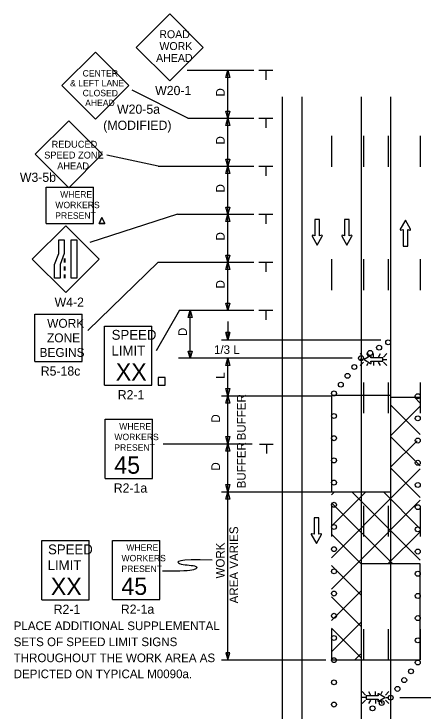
# Model space of a CAD drawing. Extents: x 16729 to 18475, y 5706 to 6927.
# Drawn here: x 16730 to 17062, y 6361 to 6927 of the extents above; entities that cross this region are included whole.
import ezdxf

# ---------------------------------------------------------------- set-up
doc = ezdxf.new("R2010")
doc.units = 0
for name, color, linetype in [('ALI_LEGAL_EX', 7, 'Continuous'), ('MT_SCRATCH_LEVEL_A', 7, 'Continuous'), ('MT_SCRATCH_LEVEL_E', 7, 'Continuous'), ('PAVT_EDGE_EX', 7, 'Continuous'), ('TRAFFIC_SIGNS_PR', 7, 'Continuous'), ('TYPICAL_TEXT_DIMEN_PR', 7, 'Continuous')]:
    doc.layers.add(name, color=color, linetype=linetype)

msp = doc.modelspace()

# ---------------------------------------------------------------- linework, layer by layer
at = {"layer": 'ALI_LEGAL_EX'}
for points in [[(16987.43, 6827.88), (16987.43, 6802.88)], [(17013.43, 6827.88), (17013.43, 6802.88)], [(17033.43, 6827.88), (17033.43, 6802.88)], [(17059.43, 6827.88), (17059.43, 6802.88)], [(16987.43, 6727.88), (16987.43, 6702.88)], [(17013.43, 6727.88), (17013.43, 6702.88)], [(17033.43, 6727.88), (17033.43, 6702.88)], [(17059.43, 6727.88), (17059.43, 6702.88)], [(17013.43, 6627.88), (17013.43, 6602.88)], [(17033.43, 6627.88), (17033.43, 6602.88)], [(17059.43, 6627.88), (17059.43, 6602.88)], [(16987.43, 6527.88), (16987.43, 6502.88)], [(17013.43, 6527.88), (17013.43, 6502.88)], [(17033.43, 6527.88), (17033.43, 6502.88)], [(17059.43, 6527.88), (17059.43, 6502.88)], [(16987.43, 6427.88), (16987.43, 6402.88)], [(17013.43, 6427.88), (17013.43, 6402.88)], [(17033.43, 6427.88), (17033.43, 6402.88)], [(17059.43, 6427.88), (17059.43, 6402.88)]]:
    msp.add_lwpolyline(points, dxfattribs=at)
at = {"layer": 'MT_SCRATCH_LEVEL_A'}
for p, q in [((17035.43, 6615.84), (17059.43, 6615.84)), ((17059.43, 6611.08), (17054.68, 6615.84)), ((17059.43, 6585.62), (17035.52, 6609.54)), ((17035.52, 6584.79), (17059.43, 6608.71)), ((17059.43, 6560.17), (17035.43, 6584.17)), ((17035.62, 6559.44), (17056.86, 6580.68)), ((17059.43, 6534.71), (17035.43, 6558.71)), ((17035.43, 6533.8), (17059.43, 6557.8)), ((16987.43, 6485.8), (17040.82, 6539.18)), ((16987.43, 6511.25), (17015.36, 6539.18)), ((16987.43, 6536.71), (16989.91, 6539.18)), ((17059.43, 6483.8), (17004.05, 6539.18)), ((17059.43, 6509.26), (17029.51, 6539.18)), ((17037.11, 6480.67), (16987.43, 6530.34)), ((17011.43, 6484.34), (17059.43, 6532.34)), ((17011.43, 6480.89), (16987.43, 6504.89)), ((17033.22, 6480.67), (17059.43, 6506.88)), ((16987.43, 6460.34), (17011.43, 6484.34)), ((17011.43, 6455.43), (16987.43, 6479.43)), ((16987.43, 6434.88), (17011.43, 6458.88)), ((17011.43, 6429.98), (16987.43, 6453.98)), ((16987.43, 6409.43), (17011.43, 6433.43)), ((17011.43, 6404.52), (16987.43, 6428.52)), ((17006.29, 6402.82), (17010.91, 6407.45)), ((16987.43, 6402.82), (17011.43, 6402.82))]:
    msp.add_line(p, q, dxfattribs=at)
at = {"layer": 'MT_SCRATCH_LEVEL_E'}
for p, q in [((16977.76, 6760.18), (16974.02, 6760.18)), ((16974.02, 6760.18), (16974.02, 6746.93)), ((16977.76, 6760.18), (16974.02, 6760.18)), ((16974.02, 6760.18), (16974.02, 6746.93)), ((16977.76, 6746.93), (16977.76, 6760.18)), ((16977.76, 6746.93), (16977.76, 6760.18)), ((17001.83, 6760.18), (16998.09, 6760.18)), ((16998.09, 6760.18), (16998.09, 6746.93)), ((17001.83, 6760.18), (16998.09, 6760.18)), ((16998.09, 6760.18), (16998.09, 6746.93)), ((17001.83, 6746.93), (17001.83, 6760.18)), ((17001.83, 6746.93), (17001.83, 6760.18)), ((17047.37, 6759.44), (17043.26, 6752.2)), ((17047.37, 6759.44), (17043.26, 6752.2)), ((17051.52, 6752.2), (17047.37, 6759.44)), ((17051.52, 6752.2), (17047.37, 6759.44)), ((17043.74, 6751.51), (17045.52, 6751.83)), ((17043.74, 6751.51), (17045.52, 6751.83)), ((17045.52, 6751.83), (17045.52, 6738.57)), ((17045.52, 6751.83), (17045.52, 6738.57)), ((17049.26, 6738.57), (17049.26, 6751.83)), ((17049.26, 6751.83), (17051.04, 6751.51)), ((17049.26, 6738.57), (17049.26, 6751.83)), ((17049.26, 6751.83), (17051.04, 6751.51)), ((16971.76, 6746.56), (16975.91, 6739.32)), ((16971.76, 6746.56), (16975.91, 6739.32)), ((16974.02, 6746.93), (16972.24, 6747.24)), ((16974.02, 6746.93), (16972.24, 6747.24)), ((16975.91, 6739.32), (16980.02, 6746.56)), ((16975.91, 6739.32), (16980.02, 6746.56)), ((16979.53, 6747.24), (16977.76, 6746.93)), ((16979.53, 6747.24), (16977.76, 6746.93)), ((16995.83, 6746.56), (16999.98, 6739.32)), ((16995.83, 6746.56), (16999.98, 6739.32)), ((16998.09, 6746.93), (16996.31, 6747.24)), ((16998.09, 6746.93), (16996.31, 6747.24)), ((16999.98, 6739.32), (17004.09, 6746.56)), ((16999.98, 6739.32), (17004.09, 6746.56)), ((17003.61, 6747.24), (17001.83, 6746.93)), ((17003.61, 6747.24), (17001.83, 6746.93)), ((17045.52, 6738.57), (17049.26, 6738.57)), ((17045.52, 6738.57), (17049.26, 6738.57)), ((16977.1, 6518.09), (16973.36, 6518.09)), ((16973.36, 6518.09), (16973.36, 6504.83)), ((16977.1, 6518.09), (16973.36, 6518.09)), ((16973.36, 6518.09), (16973.36, 6504.83)), ((16977.1, 6504.83), (16977.1, 6518.09)), ((16977.1, 6504.83), (16977.1, 6518.09)), ((16971.1, 6504.46), (16975.25, 6497.22)), ((16971.1, 6504.46), (16975.25, 6497.22)), ((16973.36, 6504.83), (16971.58, 6505.15)), ((16973.36, 6504.83), (16971.58, 6505.15)), ((16975.25, 6497.22), (16979.36, 6504.46)), ((16975.25, 6497.22), (16979.36, 6504.46)), ((16978.88, 6505.15), (16977.1, 6504.83)), ((16978.88, 6505.15), (16977.1, 6504.83))]:
    msp.add_line(p, q, dxfattribs=at)
for centre, start, end in [((17043.67, 6751.97), 150.4248, 279.9638), ((17043.67, 6751.97), 150.4248, 279.9638), ((17051.11, 6751.97), 260.0362, 29.7731), ((17051.11, 6751.97), 260.0362, 29.7731), ((16972.17, 6746.78), 80.0362, 209.7731), ((16972.17, 6746.78), 80.0362, 209.7731), ((16979.61, 6746.78), 330.4248, 99.9638), ((16979.61, 6746.78), 330.4248, 99.9638), ((16996.24, 6746.78), 80.0362, 209.7731), ((16996.24, 6746.78), 80.0362, 209.7731), ((17003.68, 6746.78), 330.4248, 99.9638), ((17003.68, 6746.78), 330.4248, 99.9638), ((16971.51, 6504.69), 80.0362, 209.7731), ((16971.51, 6504.69), 80.0362, 209.7731), ((16978.96, 6504.69), 330.4248, 99.9638), ((16978.96, 6504.69), 330.4248, 99.9638)]:
    msp.add_arc(centre, 0.463, start, end, dxfattribs=at)
at = {"layer": 'PAVT_EDGE_EX'}
for p, q in [((16947.43, 6859.63), (16947.43, 6100.51)), ((16963.43, 6859.63), (16963.43, 6100.51)), ((17011.43, 6859.63), (17011.43, 6100.51)), ((17035.43, 6859.63), (17035.43, 6100.51))]:
    msp.add_line(p, q, dxfattribs=at)
for points in [[(17035.52, 6617.36), (16987.43, 6617.36), (16987.43, 6539.18), (17035.52, 6539.18)], [(17059.43, 6480.67), (17011.43, 6480.67), (17011.43, 6402.82), (17059.43, 6402.82)]]:
    msp.add_lwpolyline(points, close=True, dxfattribs=at)
at = {"layer": 'TRAFFIC_SIGNS_PR'}
for p, q in [((16856.39, 6926.78), (16829.2, 6899.59)), ((16883.58, 6899.59), (16856.39, 6926.78)), ((16829.2, 6899.59), (16856.39, 6872.4)), ((16856.39, 6872.4), (16883.58, 6899.59)), ((16796.14, 6895.81), (16768.95, 6868.62)), ((16823.32, 6868.62), (16796.14, 6895.81)), ((16768.95, 6868.62), (16796.14, 6841.44)), ((16796.14, 6841.44), (16823.32, 6868.62)), ((16774.54, 6840.16), (16747.38, 6813.01)), ((16801.69, 6813.01), (16774.54, 6840.16)), ((16747.38, 6813.01), (16774.54, 6785.86)), ((16774.54, 6785.86), (16801.69, 6813.01)), ((16756.27, 6786.17), (16794.67, 6786.17)), ((16756.27, 6756.85), (16756.27, 6786.17)), ((16794.67, 6756.85), (16794.67, 6786.17)), ((16756.27, 6756.85), (16794.67, 6756.85)), ((16772.09, 6755.03), (16744.94, 6727.88)), ((16799.24, 6727.88), (16772.09, 6755.03)), ((16770.84, 6728.37), (16770.84, 6725.17)), ((16771.24, 6728.37), (16771.24, 6725.17)), ((16744.94, 6727.88), (16772.09, 6700.73)), ((16772.09, 6700.73), (16799.24, 6727.88)), ((16770.84, 6721.97), (16770.84, 6718.77)), ((16771.24, 6721.97), (16771.24, 6718.77)), ((16770.84, 6715.57), (16770.84, 6712.37)), ((16771.24, 6715.57), (16771.24, 6712.37)), ((16747.02, 6644.89), (16747.02, 6683.29)), ((16747.02, 6683.29), (16785.42, 6683.29)), ((16785.42, 6644.89), (16785.42, 6683.29)), ((16803.53, 6673.67), (16841.93, 6673.67)), ((16803.53, 6625.67), (16803.53, 6673.67)), ((16841.93, 6625.67), (16841.93, 6673.67)), ((17010.62, 6651.27), (17013.44, 6648.46)), ((17017.34, 6649.09), (17016.08, 6651.28)), ((17021.52, 6648.46), (17021.52, 6651.28)), ((17025.65, 6648.46), (17027.28, 6651.28)), ((17029.6, 6648.46), (17032.43, 6651.28)), ((16747.02, 6644.89), (16785.42, 6644.89)), ((17013.44, 6646.42), (17010.62, 6646.42)), ((17010.62, 6641.57), (17013.44, 6644.39)), ((17016.05, 6641.57), (17017.26, 6643.67)), ((17021.52, 6644.39), (17021.52, 6641.57)), ((17027.31, 6641.57), (17025.68, 6644.39)), ((17029.6, 6646.42), (17032.43, 6646.42)), ((17029.6, 6644.39), (17032.43, 6641.57)), ((16803.53, 6625.67), (16841.93, 6625.67)), ((16804.13, 6598.03), (16842.53, 6598.03)), ((16804.13, 6550.03), (16804.13, 6598.03)), ((16842.53, 6550.03), (16842.53, 6598.03)), ((16804.13, 6550.03), (16842.53, 6550.03)), ((16752.69, 6499.66), (16791.09, 6499.66)), ((16752.69, 6451.66), (16752.69, 6499.66)), ((16791.09, 6451.66), (16791.09, 6499.66)), ((16809.89, 6499.75), (16848.29, 6499.75)), ((16809.89, 6451.75), (16809.89, 6499.75)), ((16848.29, 6451.75), (16848.29, 6499.75)), ((16752.69, 6451.66), (16791.09, 6451.66)), ((16809.89, 6451.75), (16848.29, 6451.75)), ((17015.05, 6374.4), (17012.23, 6377.23)), ((17015.05, 6372.37), (17012.23, 6372.37)), ((17017.35, 6377.22), (17018.98, 6374.4)), ((17023.14, 6374.4), (17023.14, 6377.22)), ((17028.61, 6377.22), (17027.4, 6375.13)), ((17034.04, 6377.22), (17031.22, 6374.4)), ((17031.22, 6372.37), (17034.04, 6372.37)), ((17015.05, 6370.34), (17012.23, 6367.52)), ((17019, 6370.34), (17017.38, 6367.52)), ((17023.14, 6370.34), (17023.14, 6367.52)), ((17027.32, 6369.7), (17028.58, 6367.52)), ((17034.04, 6367.52), (17031.22, 6370.34))]:
    msp.add_line(p, q, dxfattribs=at)
for points in [[(16801.42, 6761.79), (16799.18, 6756.85)], [(16799.18, 6756.85), (16801.42, 6761.79)], [(16799.18, 6756.85), (16803.65, 6756.85)], [(16803.65, 6756.85), (16799.18, 6756.85)], [(16803.65, 6756.85), (16801.42, 6761.79)], [(16801.42, 6761.79), (16803.65, 6756.85)], [(17019.19, 6649.44), (17013.88, 6646.42), (17019.19, 6643.38)], [(17019.69, 6643.74), (17019.46, 6645.04), (17029.19, 6645.04), (17029.19, 6647.78), (17019.46, 6647.78), (17019.69, 6649.09)], [(17024.97, 6375.05), (17025.19, 6373.76), (17015.47, 6373.76), (17015.47, 6371.01), (17025.19, 6371.01), (17024.96, 6369.71)], [(17025.47, 6369.36), (17030.77, 6372.37), (17025.46, 6375.41)]]:
    msp.add_lwpolyline(points, dxfattribs=at)
for points in [[(16770.84, 6743.62), (16770.84, 6732.43), (16767.5, 6723.55), (16767.5, 6712.37), (16763, 6712.37), (16763, 6723.55), (16766.35, 6732.43), (16766.35, 6743.62)], [(16780.98, 6743.62), (16780.98, 6712.37), (16776.48, 6712.37), (16776.48, 6743.62)], [(16846.95, 6625.67), (16852.54, 6625.67), (16852.54, 6631.84), (16846.95, 6631.84)]]:
    msp.add_lwpolyline(points, close=True, dxfattribs=at)
for centre in [(17033.42, 6660.47), (17026.09, 6656.16), (17011.43, 6647.55), (17018.76, 6651.85), (17006.01, 6640.41), (17000.52, 6633.28), (16995.03, 6626.15), (16989.53, 6619.02), (17057.41, 6616.77), (16989.53, 6600.68), (17057.41, 6598.77), (16989.53, 6582.68), (17057.41, 6580.77), (16989.53, 6564.68), (17057.41, 6562.77), (16989.53, 6546.68), (17057.41, 6544.77), (16989.53, 6528.68), (17057.41, 6526.77), (16989.53, 6510.68), (17057.41, 6508.77), (16989.53, 6492.68), (17057.41, 6490.77), (16989.53, 6474.68), (17057.41, 6472.77), (16989.53, 6456.68), (17057.41, 6454.77), (16989.53, 6438.68), (17057.41, 6436.77), (16989.53, 6420.68), (17057.41, 6418.77), (16989.53, 6402.68), (17057.41, 6400.77), (17051.92, 6393.64), (16989.53, 6384.68), (17046.42, 6386.51), (17040.93, 6379.38), (17035.43, 6372.25), (16989.53, 6366.68), (17028.11, 6367.94), (17020.78, 6363.64)]:
    msp.add_circle(centre, 2, dxfattribs=at)
for centre, start, end in [((17019.36, 6649.14), 350.7308, 118.8916), ((17019.36, 6643.68), 241.4833, 9.9593), ((17025.3, 6375.11), 61.4833, 189.9593), ((17025.3, 6369.66), 170.7308, 298.8916)]:
    msp.add_arc(centre, 0.341, start, end, dxfattribs=at)
at = {"layer": 'TYPICAL_TEXT_DIMEN_PR'}
for p, q in [((16870.47, 6881.07), (16924.43, 6881.07)), ((16901.86, 6875.2), (16903.43, 6881.07)), ((16903.43, 6881.07), (16905, 6875.2)), ((16903.43, 6842.15), (16903.43, 6881.07)), ((16928.68, 6881.07), (16939.93, 6881.07)), ((16934.31, 6881.07), (16934.31, 6873.28)), ((16903.43, 6875.2), (16901.86, 6875.2)), ((16905, 6875.2), (16903.43, 6875.2)), ((16871.03, 6842.15), (16825.83, 6865.03)), ((16903.43, 6842.15), (16901.86, 6848.01)), ((16901.86, 6848.01), (16903.43, 6848.01)), ((16903.43, 6848.01), (16905, 6848.01)), ((16905, 6848.01), (16903.43, 6842.15)), ((16871.03, 6842.15), (16924.43, 6842.15)), ((16901.86, 6836.28), (16903.43, 6842.15)), ((16903.43, 6842.15), (16905, 6836.28)), ((16903.43, 6803.23), (16903.43, 6842.15)), ((16928.68, 6842.15), (16939.93, 6842.15)), ((16934.31, 6842.15), (16934.31, 6834.36)), ((16903.43, 6836.28), (16901.86, 6836.28)), ((16905, 6836.28), (16903.43, 6836.28)), ((16847.02, 6803.23), (16805.38, 6812.22)), ((16903.43, 6803.23), (16901.86, 6809.09)), ((16901.86, 6809.09), (16903.43, 6809.09)), ((16903.43, 6809.09), (16905, 6809.09)), ((16905, 6809.09), (16903.43, 6803.23)), ((16847.02, 6803.23), (16924.43, 6803.23)), ((16901.86, 6797.36), (16903.43, 6803.23)), ((16903.43, 6803.23), (16905, 6797.36)), ((16903.43, 6764.31), (16903.43, 6803.23)), ((16928.68, 6803.23), (16939.93, 6803.23)), ((16934.31, 6803.23), (16934.31, 6795.44)), ((16903.43, 6797.36), (16901.86, 6797.36)), ((16905, 6797.36), (16903.43, 6797.36)), ((16903.43, 6764.31), (16901.86, 6770.17)), ((16901.86, 6770.17), (16903.43, 6770.17)), ((16903.43, 6770.17), (16905, 6770.17)), ((16905, 6770.17), (16903.43, 6764.31)), ((16862.61, 6764.31), (16791.68, 6741.45)), ((16862.61, 6764.31), (16924.43, 6764.31)), ((16901.86, 6758.44), (16903.43, 6764.31)), ((16903.43, 6764.31), (16905, 6758.44)), ((16903.43, 6725.39), (16903.43, 6764.31)), ((16928.68, 6764.31), (16939.93, 6764.31)), ((16934.31, 6764.31), (16934.31, 6756.52)), ((16903.43, 6758.44), (16901.86, 6758.44)), ((16905, 6758.44), (16903.43, 6758.44)), ((16903.43, 6725.39), (16901.86, 6731.25)), ((16901.86, 6731.25), (16903.43, 6731.25)), ((16903.43, 6731.25), (16905, 6731.25)), ((16905, 6731.25), (16903.43, 6725.39)), ((16847.02, 6725.39), (16790.01, 6670.13)), ((16847.02, 6725.39), (16924.43, 6725.39)), ((16901.86, 6719.52), (16903.43, 6725.39)), ((16903.43, 6725.39), (16905, 6719.52)), ((16903.43, 6686.47), (16903.43, 6725.39)), ((16928.68, 6725.39), (16939.93, 6725.39)), ((16934.31, 6725.39), (16934.31, 6717.6)), ((16903.43, 6719.52), (16901.86, 6719.52)), ((16905, 6719.52), (16903.43, 6719.52)), ((16903.43, 6686.47), (16901.86, 6692.33)), ((16901.86, 6692.33), (16903.43, 6692.33)), ((16903.43, 6692.33), (16905, 6692.33)), ((16905, 6692.33), (16903.43, 6686.47)), ((16864.39, 6686.47), (16845.36, 6653.54)), ((16864.39, 6686.47), (16924.43, 6686.47)), ((16871.29, 6680.6), (16872.86, 6686.47)), ((16872.86, 6647.55), (16872.86, 6686.47)), ((16872.86, 6686.47), (16874.43, 6680.6)), ((16928.68, 6686.47), (16939.93, 6686.47)), ((16934.31, 6686.47), (16934.31, 6678.68)), ((16872.86, 6680.6), (16871.29, 6680.6)), ((16874.43, 6680.6), (16872.86, 6680.6)), ((16903.43, 6677.39), (16903.43, 6662.47)), ((16903.43, 6662.47), (16901.86, 6668.33)), ((16901.86, 6668.33), (16903.43, 6668.33)), ((16903.43, 6668.33), (16901.86, 6668.33)), ((16901.86, 6668.33), (16903.43, 6662.47)), ((16903.43, 6668.33), (16905, 6668.33)), ((16905, 6668.33), (16903.43, 6662.47)), ((16903.43, 6662.47), (16905, 6668.33)), ((16905, 6668.33), (16903.43, 6668.33)), ((16898.43, 6662.47), (17027.57, 6662.47)), ((16872.86, 6647.55), (16871.29, 6653.41)), ((16871.29, 6653.41), (16872.86, 6653.41)), ((16872.86, 6653.41), (16874.43, 6653.41)), ((16874.43, 6653.41), (16872.86, 6647.55)), ((17004.35, 6647.55), (16863.34, 6647.55)), ((17004.35, 6647.55), (16872.86, 6647.55)), ((16901.86, 6641.68), (16903.43, 6647.55)), ((16903.43, 6617.01), (16903.43, 6647.55)), ((16903.43, 6647.55), (16905, 6641.68)), ((16903.43, 6641.68), (16901.86, 6641.68)), ((16905, 6641.68), (16903.43, 6641.68)), ((16903.43, 6617.01), (16901.86, 6622.87)), ((16901.86, 6622.87), (16903.43, 6622.87)), ((16903.43, 6622.87), (16905, 6622.87)), ((16905, 6622.87), (16903.43, 6617.01)), ((16898.43, 6617.01), (16987.43, 6617.01)), ((16901.86, 6611.15), (16903.43, 6617.01)), ((16903.43, 6617.01), (16905, 6611.15)), ((16903.43, 6578.1), (16903.43, 6617.01)), ((16903.43, 6611.15), (16901.86, 6611.15)), ((16905, 6611.15), (16903.43, 6611.15)), ((17035.52, 6595.6), (17035.52, 6597.6)), ((17035.52, 6595.6), (17035.52, 6597.6)), ((16903.43, 6578.1), (16901.86, 6583.96)), ((16901.86, 6583.96), (16903.43, 6583.96)), ((16903.43, 6583.96), (16905, 6583.96)), ((16905, 6583.96), (16903.43, 6578.1)), ((16850.99, 6578.1), (16923.27, 6578.1)), ((16901.86, 6572.23), (16903.43, 6578.1)), ((16903.43, 6539.18), (16903.43, 6578.1)), ((16903.43, 6578.1), (16905, 6572.23)), ((16929.05, 6577.97), (16940.3, 6577.97)), ((16934.68, 6577.97), (16934.68, 6570.18)), ((16903.43, 6572.23), (16901.86, 6572.23)), ((16905, 6572.23), (16903.43, 6572.23)), ((16903.43, 6539.18), (16901.86, 6545.04)), ((16901.86, 6545.04), (16903.43, 6545.04)), ((16903.43, 6545.04), (16905, 6545.04)), ((16905, 6545.04), (16903.43, 6539.18)), ((16898.43, 6539.18), (16987.43, 6539.18)), ((16901.86, 6533.32), (16903.43, 6539.18)), ((16903.43, 6402.82), (16903.43, 6539.18)), ((16903.43, 6539.18), (16905, 6533.32)), ((16903.43, 6533.32), (16901.86, 6533.32)), ((16905, 6533.32), (16903.43, 6533.32)), ((16903.43, 6408.69), (16901.86, 6408.69)), ((16901.86, 6408.69), (16903.43, 6402.82)), ((16903.43, 6402.82), (16905, 6408.69)), ((16905, 6408.69), (16903.43, 6408.69)), ((16898.43, 6402.82), (16982.93, 6402.82)), ((17169.54, 6372.25), (17042.79, 6372.25))]:
    msp.add_line(p, q, dxfattribs=at)
msp.add_open_spline([(16890.63, 6483.86), (16861.11, 6484.79), (16861.46, 6479.83), (16879.69, 6479.83), (16878.53, 6475.31), (16866.2, 6474.88), (16850.4, 6474.74)], degree=3, dxfattribs=at)

# ---------------------------------------------------------------- texts
at = {"layer": 'TRAFFIC_SIGNS_PR'}
for s, height, p in [('ROAD', 6.408, (16847.92, 6907.13)), ('WORK', 6.408, (16848.03, 6897.52)), ('AHEAD', 6.408, (16845.34, 6887.91)), ('CENTER', 5.206, (16785.76, 6876.04)), ('& LEFT LANE', 5.2065, (16775.62, 6868.03)), ('CLOSED', 5.206, (16785.76, 6860.02)), ('W20-1', 7.449, (16844.55, 6860.95)), ('AHEAD', 5.206, (16787.79, 6852.01)), ('W20-5a', 7.449, (16813.63, 6845.82)), ('(MODIFIED)', 7.449, (16802.47, 6832.76)), ('REDUCED', 5.6, (16760.59, 6818.32)), ('SPEED ZONE', 5.6, (16754.59, 6809.52)), ('AHEAD', 5.6, (16765.15, 6800.72)), ('W3-5b', 7.44, (16734.89, 6790.6)), ('WHERE', 5.2, (16767.58, 6777.85)), ('WORKERS', 5.2, (16763.65, 6769.25)), ('PRESENT', 5.2, (16763.58, 6760.65)), ('W4-2', 7.44, (16763.05, 6689.29)), ('WORK', 7.217, (16757.02, 6672.25)), ('ZONE', 7.217, (16756.9, 6660.44)), ('SPEED', 8, (16809.3, 6662.53)), ('BEGINS', 7.217, (16750.83, 6648.63)), ('LIMIT', 8, (16809.14, 6649.73)), ('XX', 14.031, (16812.65, 6629.43)), ('R5-18c', 7.44, (16751.83, 6633.45)), ('R2-1', 7.44, (16814.21, 6614.23)), ('WHERE', 5.2, (16815.44, 6589.71)), ('WORKERS', 5.2, (16811.51, 6581.11)), ('PRESENT', 5.2, (16811.44, 6572.51)), ('45', 14.031, (16811.43, 6553.88)), ('R2-1a', 7.44, (16810.98, 6538.59)), ('SPEED', 8, (16757.72, 6488.53)), ('WHERE', 5.2, (16821.2, 6491.44)), ('WORKERS', 5.2, (16817.27, 6482.84)), ('LIMIT', 8, (16757.39, 6475.73)), ('PRESENT', 5.2, (16817.2, 6474.24)), ('XX', 14.031, (16760, 6455.42)), ('45', 14.031, (16817.19, 6455.61)), ('R2-1', 7.44, (16762.3, 6440.22)), ('R2-1a', 7.44, (16816.74, 6440.31)), ('PLACE ADDITIONAL SUPPLEMENTAL', 7, (16729.89, 6427.05)), ('SETS OF SPEED LIMIT SIGNS', 7, (16729.89, 6414.05)), ('THROUGHOUT THE WORK AREA AS', 7, (16729.89, 6401.05)), ('DEPICTED ON TYPICAL M0090a.', 7, (16729.89, 6388.05))]:
    msp.add_text(s, height=height, dxfattribs=at).set_placement(p)
at = {"layer": 'TYPICAL_TEXT_DIMEN_PR'}
for s, p in [('D', (16900.88, 6859.81)), ('D', (16900.88, 6820.89)), ('D', (16900.88, 6781.97)), ('D', (16900.88, 6743.05)), ('D', (16900.88, 6704.13)), ('D', (16870.3, 6665.51)), ('L', (16900.88, 6630.88)), ('BUFFER', (16917.94, 6580.97)), ('D', (16897.11, 6595.32)), ('BUFFER', (16917.94, 6542.05)), ('D', (16897.11, 6556.41)), ('AREA VARIES', (16911.81, 6448.71)), ('WORK', (16900.81, 6468.95))]:
    msp.add_text(s, height=7, rotation=90, dxfattribs=at).set_placement(p)
msp.add_text('1/3 L', height=7, dxfattribs=at).set_placement((16892.22, 6651))

doc.saveas('drawing.dxf')
